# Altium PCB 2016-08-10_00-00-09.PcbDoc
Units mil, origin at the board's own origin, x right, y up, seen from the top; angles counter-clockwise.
Board outline 3000 x 1850 mil, 4 copper layers (Top Layer, MidLayer1, MidLayer2, Bottom Layer); 13 components, 9 nets, 30 pads, 45 vias.
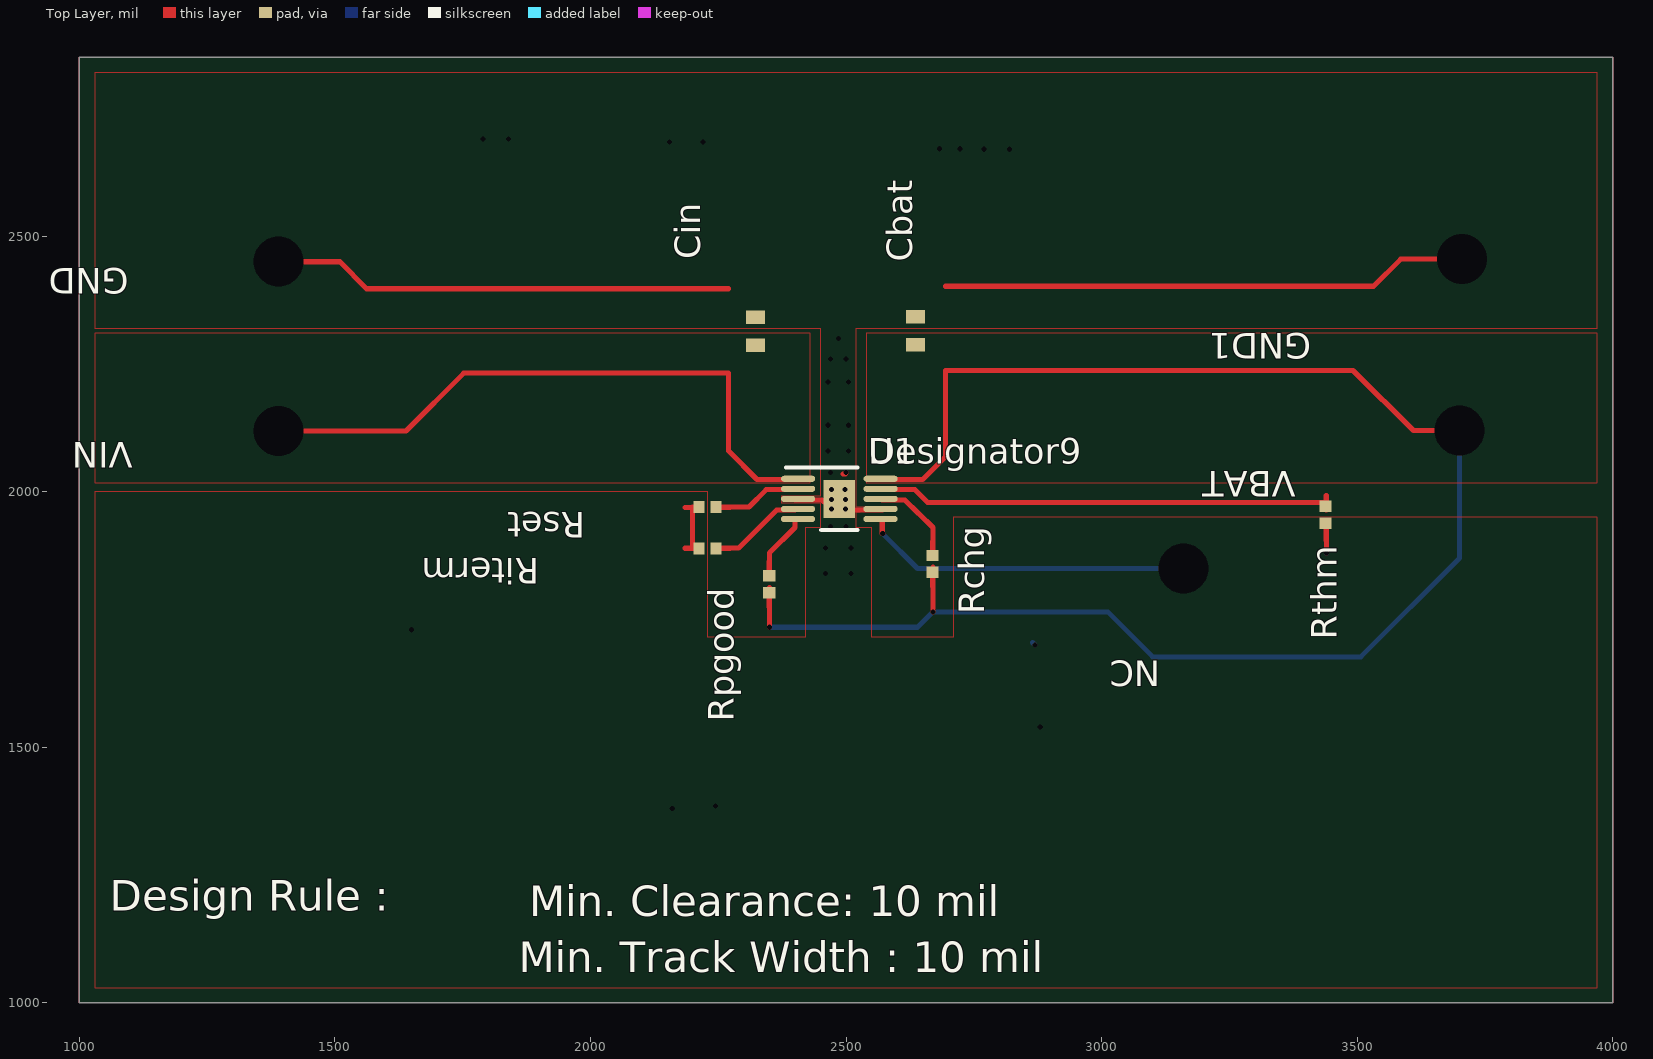
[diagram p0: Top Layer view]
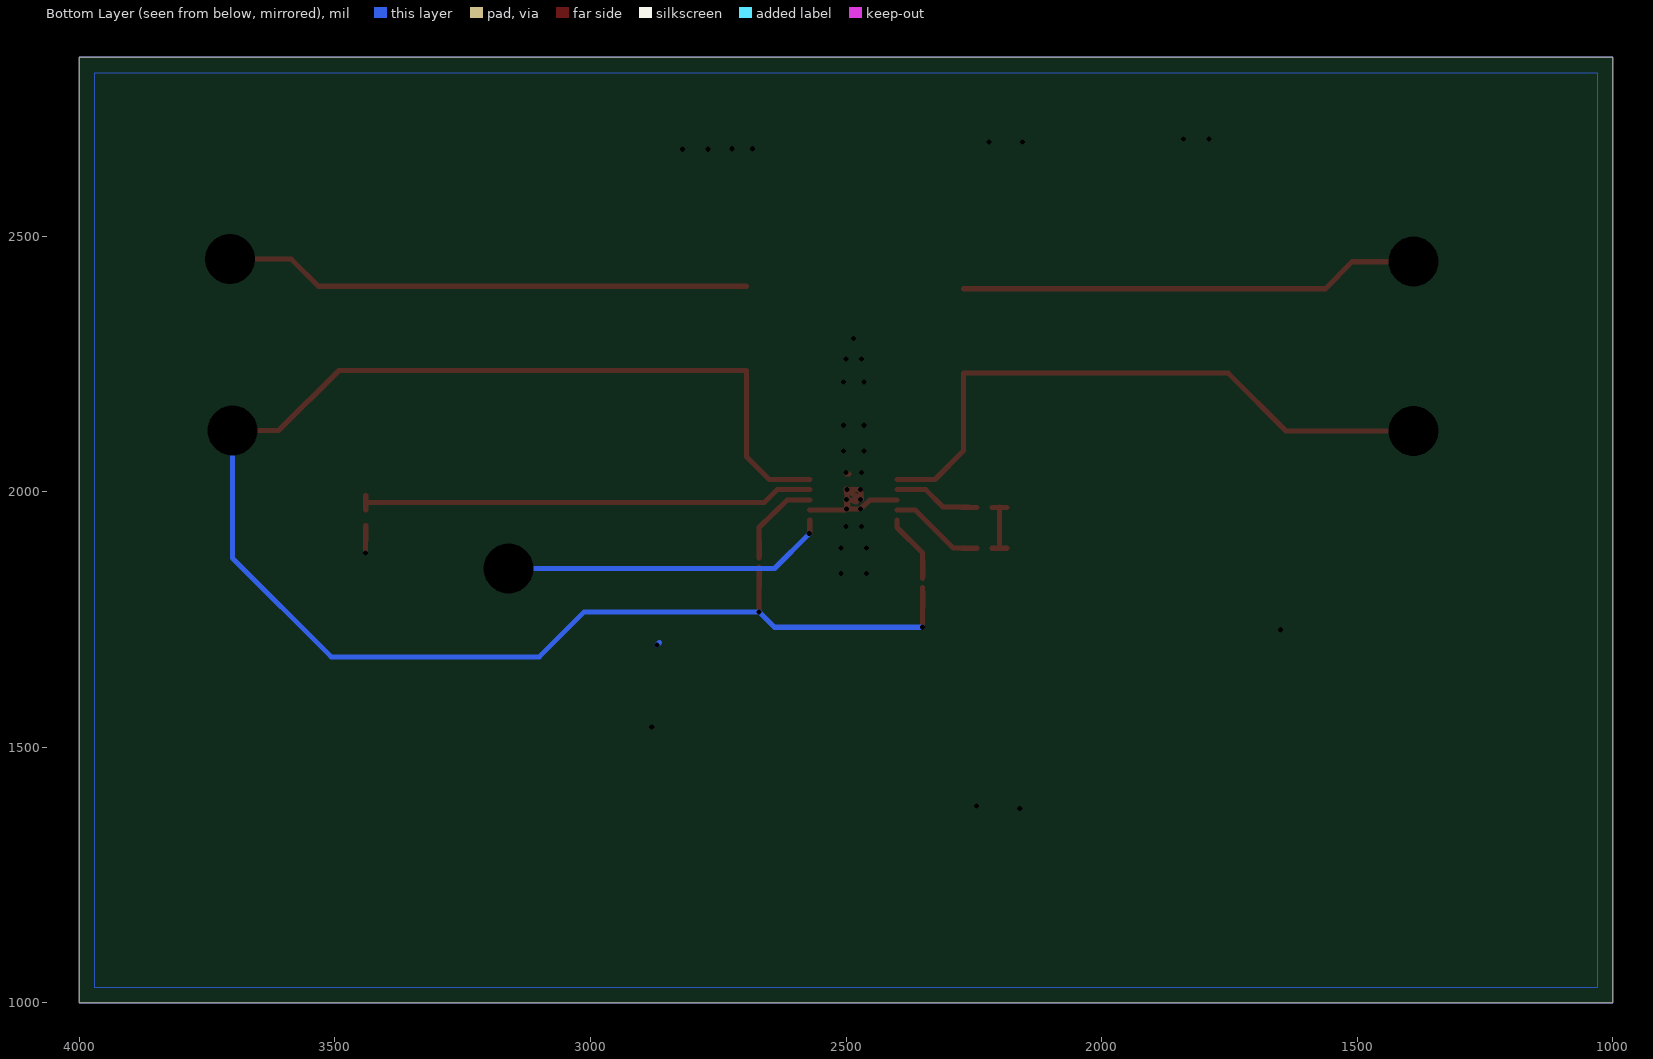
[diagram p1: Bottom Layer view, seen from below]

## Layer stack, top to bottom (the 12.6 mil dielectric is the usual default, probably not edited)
Top Layer: signal copper 1.4
Dielectric: core 12.6, FR-4, Dk 4.8
MidLayer1: signal copper 1.4
Dielectric: prepreg 12.6, FR-4, Dk 4.8
MidLayer2: signal copper 1.4
Dielectric: core 12.6, FR-4, Dk 4.8
Bottom Layer: signal copper 1.4

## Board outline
1000,1000 4000,1000 4000,2850 1000,2850

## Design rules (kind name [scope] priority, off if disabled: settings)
PlaneConnect [All] p0: scope1count=1 scope1_0_kind=Board scope1_0_value=Board scope2count=1 scope2_0_kind=Board scope2_0_value=Board commentlength=0 planeconnectstyle=Direct reliefexpansion=20 reliefentries=4 reliefconductorwidth=10 reliefairgap=10
PlaneConnect [All] p1: planeconnectstyle=Direct reliefexpansion=20 reliefentries=4 reliefconductorwidth=10 reliefairgap=10
PolygonConnect [All] p0: scope1count=1 scope1_0_kind=Board scope1_0_value=Board scope2count=1 scope2_0_kind=Board scope2_0_value=Board commentlength=0 connectstyle=Direct reliefconductorwidth=10 reliefentries=4 polygonreliefangle="90 Angle"
PolygonConnect [All] p1: connectstyle=Direct reliefconductorwidth=10 reliefentries=4 polygonreliefangle="90 Angle"

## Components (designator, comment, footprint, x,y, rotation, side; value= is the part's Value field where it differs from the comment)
Cbat "" 0603 2636,2315 r90 top
Cin "" 0603 2323,2314 r90 top
GND "" TP-1502 1389,2449 r180 top
GND1 "" TP-1502 3704,2454 r180 top
NC "" TP-1502 3159,1850 r180 top
Rchg "" 0402 2669,1859 r90 top
Riterm "" 0402 2229,1889 r180 top
Rpgood "" 0402 2350,1819 r90 top
Rset "" 0402 2229,1970 r180 top
Rthm "" 0402 3438,1955 r90 top
U1 "" DGQ0010D_NV_N 2487,1986 r0 top
VBAT "" TP-1502 3699,2120 r180 top
VIN "" TP-1502 1389,2118 r180 top

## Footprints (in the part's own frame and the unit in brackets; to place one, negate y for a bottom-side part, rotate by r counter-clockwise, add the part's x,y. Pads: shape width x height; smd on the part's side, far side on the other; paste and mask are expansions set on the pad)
0402 [mil]
  rect 22x24 smd: 1(-16.5,0) 2(16.5,0)
0603 [mil]
  rect 26x38 smd: 1(-27.5,0) 2(27.5,0)
DGQ0010D_NV_N [mm]
  oval 1.7x0.3 smd: 1(-2.05,1) 2(-2.05,0.5) 3(-2.05,0) 4(-2.05,-0.5) 5(-2.05,-1) 6(2.05,-1) 7(2.05,-0.5) 8(2.05,0) 9(2.05,0.5) 10(2.05,1)
  rect 1.57x1.88 smd: 11(0,0)
  silkscreen extent -2.65,-1.55 0.9,1.55
TP-1502 [mil]
  round 65 / inner round 0 / far side round 65 hole 32: 1(0,0)

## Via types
v1: diameter 0, hole 10, Top Layer to Bottom Layer, 40 vias
v2: diameter 0, hole 98, Top Layer to Bottom Layer, 5 vias

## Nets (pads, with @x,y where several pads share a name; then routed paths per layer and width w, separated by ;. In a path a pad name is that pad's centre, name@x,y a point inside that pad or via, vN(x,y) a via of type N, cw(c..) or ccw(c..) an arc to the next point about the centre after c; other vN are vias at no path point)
0: Cbat.2 Cin.2 GND1.1 GND.1 Riterm.2 Rset.2 Rthm.1 U1.3 U1.7 U1.11 | length 2553.8
  Top Layer w9: U1.11@2470,1985 v1(2472,1985)
  Top Layer w10: v2(1390,2450) 1510,2450 1562,2397 2270,2397 ; 2185,1889.5 Riterm.2@2214,1889.5 ; 2185,1969.5 Rset.2@2214,1969.5 ; 2200,1890 2200,1970 ; U1.3@2400,1984 2453,1984 v1(2472,1966) v1(2499,1966) ; v1(2472,1985) U1.11@2472,1986 ; U1.11@2485,1985 2480,1980 2486,1982 2495,1985 U1.11@2497,1985 ; 2494,2035 2499,2035 v1(2500,2038) ; v1(2498,2004) v1(2472,2004) ; U1.7@2571,1964 2500,1964 v1(2499,1966) ; 2695,2402 3532,2402 3585,2455 v2(3705,2455) ; 3439.5,1905 Rthm.1@3439.5,1934 ; v1(3440,1880) 3440,1920 ; U1.11@2472,1986 v1(2472,2004) ; U1.11@2472,1986 2471,1985 2470,1985 2470,1986 v1(2472,2004) ; U1.11@2472,1986 2480,1991 2498,2003 2500,2005 U1.11@2497,1985 ; U1.11@2496,1970 U1.11@2499,1980 ; U1.11@2496,1970 U1.11@2499,1981 ; U1.11@2496,1970 2497,1983 U1.11@2497,1985 ; U1.11@2497,1985 v1(2499,1985) ; v1(2499,1966) U1.11@2499,1980 ; U1.11@2499,1980 U1.11@2499,1981 ; U1.11@2499,1980 U1.11@2500,1984 ; U1.11@2499,1981 v1(2499,1985) ; U1.11@2499,1981 U1.11@2499,1984 ; U1.11@2499,1984 v1(2499,1985) ; U1.11@2499,1984 U1.11@2500,1985 ; U1.11@2499,1984 U1.11@2500,1984 ; v1(2499,1985) U1.11@2500,1985 ; U1.11@2500,1984 U1.11@2500,1985
  Bottom Layer w10: 2865,1705 v1(2870,1700)
  other v1: 2160,1380 2245,1385 2880,1540 1650,1730 2460,1840 2510,1840 2460,1890 2510,1890 2470,1932 2500,1932 2470,2038 2465,2080 2505,2080 2465,2130 2505,2130 2465,2215 2505,2215 2470,2260 2500,2260 2485,2300 2770,2670 2820,2670 2683,2671 2723,2671 2155,2684 2220,2684 1790,2690 1840,2690
5: Cbat.1 Rchg.1 Rpgood.1 U1.10 VBAT.1 | length 3316.6
  Top Layer w10: 2349.5,1775 Rpgood.1@2349.5,1804 ; v1(2350,1735) 2350,1790 Rpgood.1@2350,1813 ; U1.10@2571,2024 2650,2024 2695,2069 2695,2237 3492,2237 3610,2120 v2(3700,2120) ; 2669.5,1815 Rchg.1@2669.5,1844 ; v1(2670,1765) 2670,1830 Rchg.1@2670,1853
  Bottom Layer w10: v1(2350,1735) 2640,1735 v1(2670,1765) 3012,1765 3100,1677 3507,1677 3700,1870 v2(3700,2120)
6: Cin.1 U1.1 VIN.1 | length 1232
  Top Layer w10: v2(1390,2119) 1639,2119 1752,2232 2270,2232 2270,2080 2326,2024 U1.1@2400,2024
7: Rset.1 U1.2 | length 184.1
  Top Layer w10: Rset.1@2244,1969.5 2273,1969.5 ; 2259,1970 2310,1970 2344,2004 U1.2@2400,2004
8: NC.1 U1.6 | length 644.2
  Top Layer w10: U1.6@2571,1945 2571,1918 v1(2572,1918)
  Bottom Layer w10: v1(2572,1918) 2640,1850 v2(3160,1850)
9: Riterm.1 U1.4 | length 200.7
  Top Layer w10: Riterm.1@2244,1889.5 2273,1889.5 ; 2259,1890 2290,1890 2364,1964 U1.4@2400,1964
10: Rchg.2 U1.8 | length 210.1
  Top Layer w10: U1.8@2571,1984 2615,1984 2670,1930 2670,1889 Rchg.2@2670,1870 ; Rchg.2@2669.5,1874 2669.5,1903
13: Rpgood.2 U1.5 | length 164.7
  Top Layer w10: Rpgood.2@2349.5,1834 2349.5,1863 ; Rpgood.2@2350,1830 2350,1849 2350,1880 2400,1930 U1.5@2400,1945
15: Rthm.2 U1.9 | length 908.4
  Top Layer w10: U1.9@2571,2004 2635,2004 2660,1979 Rthm.2@3440,1979 ; Rthm.2@3439.5,1964 3439.5,1993

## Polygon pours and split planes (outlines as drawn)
5 on Top Layer " " (solid, pour order 0): 2540,2018 3970,2018 3970,2310 2540,2310
6 on Top Layer " " (solid, pour order 1): 1030,2018 2430,2018 2430,2310 1030,2310
0 on Top Layer " " (solid, pour order 3): 3970,2320 3970,2820 1030,2820 1030,2320 2450,2320 2450,1991 2373,1991 2373,1978 2450,1978 2450,1930 2420,1930 2420,1715 2230,1715 2230,2000 1030,2000 1030,1030 3970,1030 3970,1950 2710,1950 2710,1715 2550,1715 2550,1930 2520,1930 2520,1960 2599,1970 2520,1970 2520,2320
0 on Bottom Layer " " (solid, pour order 2): 3970,1030 3970,2820 1030,2820 1030,1030

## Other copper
Multi-Layer:
  the board outline again, w1

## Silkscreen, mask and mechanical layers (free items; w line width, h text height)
Top Overlay:
  text "Design Rule :" at 1060,1180 h60
  text "Min. Clearance: 10 mil" at 1880,1170 h60
  text "Min. Track Width : 10 mil" at 1860,1060 h60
